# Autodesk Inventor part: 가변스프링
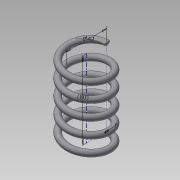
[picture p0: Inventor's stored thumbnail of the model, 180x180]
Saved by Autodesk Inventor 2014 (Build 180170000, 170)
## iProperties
Created: 2019-10
Part Number: 가변스프링
Material: 일반
Document SubType Name: Modeling
Designer: net
Density: 1 g/cm^3
Appearance: 기본값
Author: net
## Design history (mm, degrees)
sketch "스케치1"
  geometry: L1 (0, 0)-(21, 0); L2 (21, 0)-(21, 80); L3 (21, 80)-(0, 80); L4 (0, 80)-(0, 0); C1 r 3 at (21, 0)
  constraints: 8 end point, 2 parallel, 1 centre point, 1 coincident, 1 horizontal, 1 perpendicular
  dimensions: "d0" = 80 distance of L3.end L1.start (derived); "d1" = 42 diameter of L2 L4; "d2" = 6 diameter of C1
feature "코일1" sketch "스케치1" pitch "d3" = 10; turns "d5" = 5; dims "d4" = 80 (= d0), "d6" = 0, angle "d7" = 90 deg, angle "d8" = 90 deg, "d9" = 0, "d10" = 0
sketch "스케치2"
  geometry: L1 (24, 80)-(24, 83); L2 (24, 83)-(-21.483, 83); L3 (-21.483, 83)-(-21.483, 80); L4 (-21.483, 80)-(24, 80); 2 further points
  constraints: 8 end point, 3 perpendicular, 2 vertical, 1 horizontal alignment
extrude "돌출1" cut sketch "스케치2" distance "d11" = 50.25; taper "d12" = 0 deg
sketch "스케치3"
  geometry: L1 (24, 0)-(24, -3); L2 (24, -3)-(-30.191, -3); L3 (-30.191, -3)-(-30.191, 0); L4 (-30.191, 0)-(24, 0); 2 further points
  constraints: 8 end point, 2 perpendicular, 2 vertical, 1 horizontal alignment
extrude "돌출2" cut sketch "스케치3" distance "d13" = 50.25; taper "d14" = 0 deg
node "솔리드1"
